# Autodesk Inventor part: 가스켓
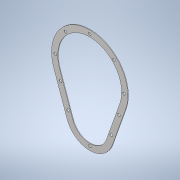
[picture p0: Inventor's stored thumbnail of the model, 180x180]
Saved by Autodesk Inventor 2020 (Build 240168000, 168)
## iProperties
Created: 2024-05
Part Number: 가스켓
Material: 스테인리스스틸
Document SubType Name: Modeling
Designer: oem
Density: 8 g/cm^3
Appearance: 기본값
Author: jhkim
Sending System: Autodesk Inventor 2025
Preprocessor: ST-DEVELOPER v20
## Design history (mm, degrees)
node "가스켓1"
node "솔리드2"
node "솔리드1"
